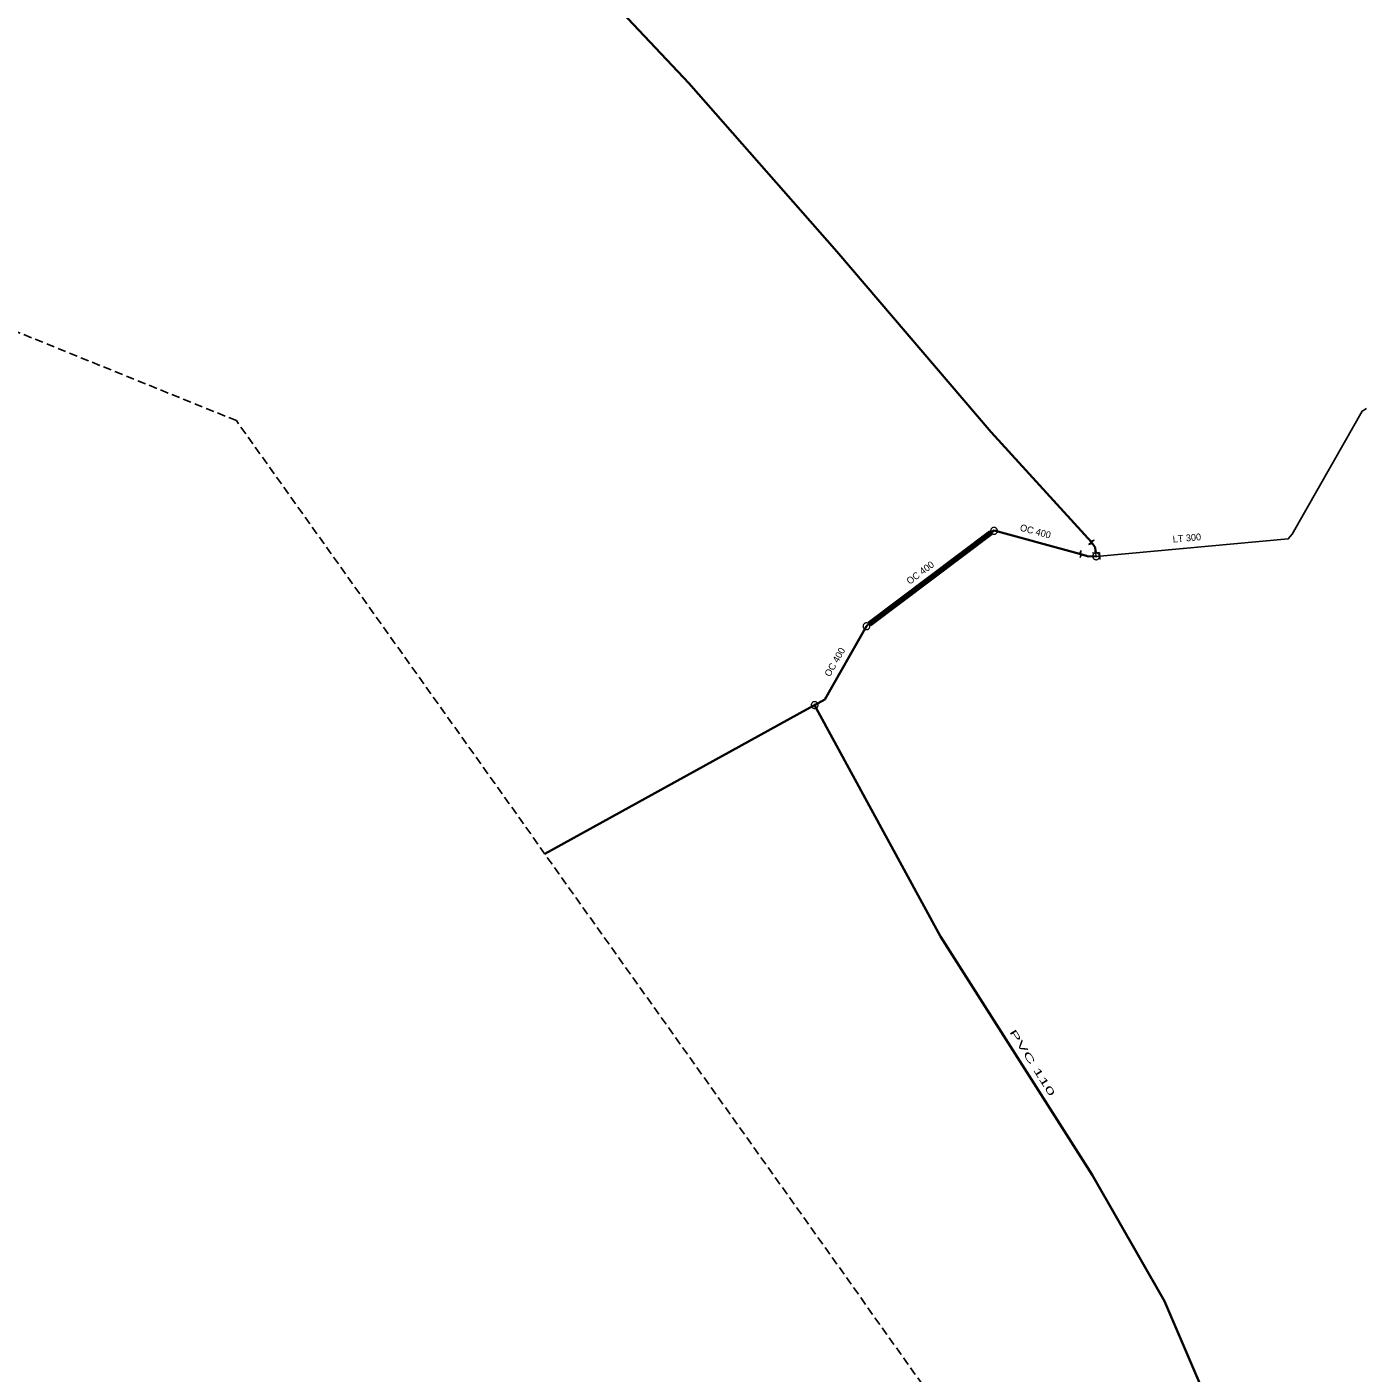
# Model space of a CAD drawing. Extents: x -724334 to -723692, y -972150 to -970648.
# Drawn here: x -724012.8 to -723816.8, y -971399.3 to -971202 of the extents above; entities that cross this region are included whole.
import ezdxf

# ---------------------------------------------------------------- set-up
doc = ezdxf.new("R2010")
doc.units = 0
doc.header["$LTSCALE"] = 0.4
doc.linetypes.add('MEDIUM_DASHED', pattern=[4.5, 3, -1.5])
for name, color, linetype, lineweight in [('1', 7, 'Continuous', 25), ('14', 7, 'Continuous', 25), ('17', 7, 'Continuous', 35), ('23', 7, 'Continuous', 13), ('3', 7, 'Continuous', 106), ('34', 7, 'Continuous', 13), ('47', 7, 'Continuous', 13)]:
    doc.layers.add(name, color=color, linetype=linetype, lineweight=lineweight)

msp = doc.modelspace()

# ---------------------------------------------------------------- linework, layer by layer
at = {"layer": '1', "linetype": 'MEDIUM_DASHED'}
msp.add_lwpolyline([(-723848.074, -970648.428), (-723714.095, -970720.999), (-724065.788, -971064.318), (-723792.249, -971201.088), (-723702.93, -971508.122), (-723691.766, -972150.101), (-723842.491, -972097.068), (-723864.821, -971424.385), (-723982.052, -971259.703), (-724333.745, -971117.352)], close=True, dxfattribs=at)
at = {"layer": '14', "lineweight": 13}
for q in [(-723856.14, -971279.03), (-723855.55, -971279.539)]:
    msp.add_line((-723856.079, -971279.579), q, dxfattribs=at)
at = {"layer": '17'}
for points in [[(-723856.75, -971277.52), (-723871.469, -971261.379), (-723894.09, -971234.91), (-723915.739, -971210.25), (-723934.449, -971190.379), (-723958.59, -971177.719), (-723983.8, -971165.17), (-724007.629, -971153.55), (-724038.03, -971139.35), (-724069.469, -971127.41), (-724098.62, -971120.079), (-724100.07, -971119.51), (-724120.89, -971115.66), (-724149.294, -971109.225), (-724187.32, -971097.32), (-724220.714, -971087.254)], [(-723889.699, -971289.809), (-723889.26, -971289.449), (-723871.489, -971276.09), (-723871.01, -971275.82)], [(-723871.01, -971275.82), (-723858.829, -971279.129), (-723858.359, -971279.26)], [(-723856.14, -971279.03), (-723856.17, -971278.77), (-723856.23, -971278.289), (-723856.75, -971277.52)], [(-723858.359, -971279.26), (-723857.5, -971279.51), (-723857.25, -971279.629), (-723856.079, -971279.579)], [(-723897.32, -971301.379), (-723895.809, -971300.579), (-723889.699, -971289.809)], [(-723936.882, -971323.157), (-723898.52, -971302.02), (-723897.32, -971301.379)], [(-723897.32, -971301.379), (-723897.12, -971301.809), (-723878.899, -971335.289), (-723856.64, -971370.239), (-723846.059, -971388.75), (-723832.309, -971420.76), (-723822.829, -971446.28), (-723817.91, -971463.35), (-723817.129, -971471.1), (-723816.85, -971479.71), (-723817.559, -971487.479)]]:
    msp.add_lwpolyline(points, dxfattribs=at)
at = {"layer": '17', "lineweight": 25}
msp.add_lwpolyline([(-723855.55, -971279.539), (-723827.91, -971277.02), (-723827.35, -971276.35), (-723819.71, -971262.93), (-723817.079, -971258.3), (-723816.43, -971257.91)], dxfattribs=at)
at = {"layer": '23'}
for points in [[(-723870.533, -971275.837), (-723870.536, -971275.784), (-723870.545, -971275.732), (-723870.56, -971275.683), (-723870.579, -971275.634), (-723870.603, -971275.588), (-723870.633, -971275.544), (-723870.666, -971275.504), (-723870.703, -971275.468), (-723870.744, -971275.435), (-723870.788, -971275.407), (-723870.835, -971275.383), (-723870.885, -971275.365), (-723870.935, -971275.352), (-723870.986, -971275.345), (-723871.038, -971275.342), (-723871.092, -971275.346), (-723871.142, -971275.354), (-723871.194, -971275.369), (-723871.241, -971275.387), (-723871.288, -971275.411), (-723871.332, -971275.442), (-723871.372, -971275.475), (-723871.409, -971275.513), (-723871.442, -971275.553), (-723871.469, -971275.597), (-723871.492, -971275.645), (-723871.51, -971275.693), (-723871.523, -971275.744), (-723871.53, -971275.796), (-723871.533, -971275.848), (-723871.53, -971275.9), (-723871.521, -971275.952), (-723871.507, -971276.003), (-723871.488, -971276.051), (-723871.463, -971276.096), (-723871.434, -971276.14), (-723871.401, -971276.181), (-723871.363, -971276.218), (-723871.322, -971276.25)], [(-723871.194, -971275.369), (-723871.241, -971275.387), (-723871.288, -971275.411), (-723871.332, -971275.442), (-723871.372, -971275.475), (-723871.409, -971275.513), (-723871.442, -971275.553), (-723871.469, -971275.597), (-723871.492, -971275.645), (-723871.51, -971275.693), (-723871.523, -971275.744), (-723871.53, -971275.796), (-723871.533, -971275.848), (-723871.53, -971275.9), (-723871.521, -971275.952), (-723871.507, -971276.003), (-723871.488, -971276.051), (-723871.463, -971276.096), (-723871.434, -971276.14), (-723871.401, -971276.181), (-723871.363, -971276.218), (-723871.322, -971276.25), (-723871.279, -971276.278), (-723871.231, -971276.301), (-723871.183, -971276.32), (-723871.131, -971276.332), (-723871.08, -971276.339), (-723871.028, -971276.342), (-723870.976, -971276.338), (-723870.924, -971276.33), (-723870.873, -971276.316), (-723870.825, -971276.296), (-723870.778, -971276.272), (-723870.735, -971276.244), (-723870.695, -971276.209), (-723870.658, -971276.173), (-723870.626, -971276.132), (-723870.597, -971276.087), (-723870.574, -971276.04), (-723870.556, -971275.991)], [(-723871.322, -971276.25), (-723871.279, -971276.278), (-723871.231, -971276.301), (-723871.183, -971276.32), (-723871.131, -971276.332), (-723871.08, -971276.339), (-723871.028, -971276.342), (-723870.976, -971276.338), (-723870.924, -971276.33), (-723870.873, -971276.316), (-723870.825, -971276.296), (-723870.778, -971276.272), (-723870.735, -971276.244), (-723870.695, -971276.209), (-723870.658, -971276.173), (-723870.626, -971276.132), (-723870.597, -971276.087), (-723870.574, -971276.04), (-723870.556, -971275.991), (-723870.544, -971275.94), (-723870.536, -971275.889), (-723870.533, -971275.837), (-723870.536, -971275.784), (-723870.545, -971275.732), (-723870.56, -971275.683), (-723870.579, -971275.634), (-723870.603, -971275.588), (-723870.633, -971275.544), (-723870.666, -971275.504), (-723870.703, -971275.468), (-723870.744, -971275.435), (-723870.788, -971275.407), (-723870.835, -971275.383), (-723870.885, -971275.365), (-723870.935, -971275.352), (-723870.986, -971275.345), (-723871.038, -971275.342), (-723871.092, -971275.346), (-723871.142, -971275.354), (-723871.194, -971275.369)], [(-723870.556, -971275.991), (-723870.544, -971275.94), (-723870.536, -971275.889), (-723870.533, -971275.837)], [(-723889.223, -971289.827), (-723889.225, -971289.774), (-723889.235, -971289.722), (-723889.25, -971289.673), (-723889.269, -971289.624), (-723889.293, -971289.578), (-723889.323, -971289.534), (-723889.355, -971289.494), (-723889.392, -971289.458), (-723889.434, -971289.425), (-723889.478, -971289.397), (-723889.524, -971289.373), (-723889.575, -971289.355), (-723889.625, -971289.342), (-723889.676, -971289.335), (-723889.728, -971289.332), (-723889.782, -971289.336), (-723889.831, -971289.344), (-723889.884, -971289.359), (-723889.931, -971289.377), (-723889.978, -971289.401), (-723890.022, -971289.432), (-723890.061, -971289.465), (-723890.098, -971289.503), (-723890.132, -971289.543), (-723890.159, -971289.587), (-723890.181, -971289.635), (-723890.2, -971289.683), (-723890.213, -971289.734), (-723890.22, -971289.786), (-723890.223, -971289.838), (-723890.22, -971289.89), (-723890.211, -971289.942), (-723890.196, -971289.993), (-723890.178, -971290.041), (-723890.152, -971290.086), (-723890.124, -971290.13), (-723890.09, -971290.171), (-723890.053, -971290.208), (-723890.012, -971290.24)], [(-723889.884, -971289.359), (-723889.931, -971289.377), (-723889.978, -971289.401), (-723890.022, -971289.432), (-723890.061, -971289.465), (-723890.098, -971289.503), (-723890.132, -971289.543), (-723890.159, -971289.587), (-723890.181, -971289.635), (-723890.2, -971289.683), (-723890.213, -971289.734), (-723890.22, -971289.786), (-723890.223, -971289.838), (-723890.22, -971289.89), (-723890.211, -971289.942), (-723890.196, -971289.993), (-723890.178, -971290.041), (-723890.152, -971290.086), (-723890.124, -971290.13), (-723890.09, -971290.171), (-723890.053, -971290.208), (-723890.012, -971290.24), (-723889.968, -971290.268), (-723889.921, -971290.291), (-723889.872, -971290.31), (-723889.821, -971290.322), (-723889.769, -971290.329), (-723889.718, -971290.332), (-723889.666, -971290.328), (-723889.614, -971290.32), (-723889.563, -971290.306), (-723889.514, -971290.286), (-723889.468, -971290.262), (-723889.424, -971290.234), (-723889.385, -971290.199), (-723889.348, -971290.163), (-723889.316, -971290.122), (-723889.287, -971290.077), (-723889.264, -971290.03), (-723889.245, -971289.981)], [(-723890.012, -971290.24), (-723889.968, -971290.268), (-723889.921, -971290.291), (-723889.872, -971290.31), (-723889.821, -971290.322), (-723889.769, -971290.329), (-723889.718, -971290.332), (-723889.666, -971290.328), (-723889.614, -971290.32), (-723889.563, -971290.306), (-723889.514, -971290.286), (-723889.468, -971290.262), (-723889.424, -971290.234), (-723889.385, -971290.199), (-723889.348, -971290.163), (-723889.316, -971290.122), (-723889.287, -971290.077), (-723889.264, -971290.03), (-723889.245, -971289.981), (-723889.233, -971289.93), (-723889.225, -971289.879), (-723889.223, -971289.827), (-723889.225, -971289.774), (-723889.235, -971289.722), (-723889.25, -971289.673), (-723889.269, -971289.624), (-723889.293, -971289.578), (-723889.323, -971289.534), (-723889.355, -971289.494), (-723889.392, -971289.458), (-723889.434, -971289.425), (-723889.478, -971289.397), (-723889.524, -971289.373), (-723889.575, -971289.355), (-723889.625, -971289.342), (-723889.676, -971289.335), (-723889.728, -971289.332), (-723889.782, -971289.336), (-723889.831, -971289.344), (-723889.884, -971289.359)], [(-723889.245, -971289.981), (-723889.233, -971289.93), (-723889.225, -971289.879), (-723889.223, -971289.827)]]:
    msp.add_lwpolyline(points, dxfattribs=at)
at = {"layer": '3'}
msp.add_line((-723889.26, -971289.45), (-723871.49, -971276.09), dxfattribs=at)
at = {"layer": '3', "lineweight": 100}
msp.add_line((-723889.26, -971289.45), (-723871.49, -971276.09), dxfattribs=at)
at = {"layer": '34'}
for p, q in [((-723856.636, -971279.084), (-723855.642, -971278.976)), ((-723855.588, -971279.04), (-723855.512, -971280.037))]:
    msp.add_line(p, q, dxfattribs=at)
at = {"layer": '47'}
for p, q in [((-723856.351, -971277.202), (-723856.842, -971277.341)), ((-723858.32, -971278.751), (-723858.552, -971279.206))]:
    msp.add_line(p, q, dxfattribs=at)
for points in [[(-723856.351, -971277.202), (-723857.148, -971277.837), (-723856.657, -971277.698)], [(-723858.32, -971278.751), (-723858.397, -971279.768), (-723858.165, -971279.313)]]:
    msp.add_lwpolyline(points, dxfattribs=at)
for points in [[(-723855.579, -971279.557), (-723855.584, -971279.505), (-723855.594, -971279.454), (-723855.611, -971279.404), (-723855.631, -971279.356), (-723855.657, -971279.31), (-723855.687, -971279.268), (-723855.722, -971279.229), (-723855.761, -971279.194), (-723855.802, -971279.162), (-723855.847, -971279.135), (-723855.895, -971279.113), (-723855.945, -971279.097), (-723855.995, -971279.086), (-723856.048, -971279.08), (-723856.1, -971279.079), (-723856.152, -971279.084), (-723856.203, -971279.094), (-723856.254, -971279.111), (-723856.301, -971279.131), (-723856.347, -971279.157), (-723856.389, -971279.187), (-723856.429, -971279.222), (-723856.464, -971279.261), (-723856.496, -971279.302), (-723856.522, -971279.347), (-723856.544, -971279.395), (-723856.561, -971279.445), (-723856.571, -971279.495), (-723856.577, -971279.548), (-723856.578, -971279.6), (-723856.573, -971279.652), (-723856.563, -971279.703), (-723856.547, -971279.754), (-723856.526, -971279.801), (-723856.5, -971279.847), (-723856.471, -971279.89), (-723856.436, -971279.929), (-723856.397, -971279.964), (-723856.355, -971279.996), (-723856.31, -971280.022), (-723856.262, -971280.044), (-723856.213, -971280.061), (-723856.162, -971280.071), (-723856.109, -971280.077), (-723856.057, -971280.078), (-723856.005, -971280.073), (-723855.954, -971280.063), (-723855.904, -971280.047), (-723855.856, -971280.026), (-723855.81, -971280), (-723855.767, -971279.971), (-723855.729, -971279.936), (-723855.694, -971279.897), (-723855.662, -971279.855), (-723855.635, -971279.81), (-723855.613, -971279.762), (-723855.597, -971279.713), (-723855.586, -971279.662), (-723855.58, -971279.609)], [(-723855.997, -971279.575), (-723855.997, -971279.566), (-723855.999, -971279.558), (-723856.002, -971279.55), (-723856.005, -971279.542), (-723856.009, -971279.535), (-723856.015, -971279.528), (-723856.02, -971279.521), (-723856.026, -971279.515), (-723856.033, -971279.511), (-723856.041, -971279.506), (-723856.049, -971279.502), (-723856.057, -971279.5), (-723856.065, -971279.498), (-723856.073, -971279.496), (-723856.082, -971279.497), (-723856.091, -971279.497), (-723856.099, -971279.499), (-723856.107, -971279.502), (-723856.115, -971279.505), (-723856.122, -971279.509), (-723856.129, -971279.515), (-723856.136, -971279.52), (-723856.142, -971279.526), (-723856.147, -971279.533), (-723856.151, -971279.541), (-723856.155, -971279.549), (-723856.157, -971279.557), (-723856.159, -971279.565), (-723856.161, -971279.573), (-723856.16, -971279.582), (-723856.16, -971279.591), (-723856.158, -971279.599), (-723856.155, -971279.607), (-723856.152, -971279.615), (-723856.148, -971279.622), (-723856.143, -971279.629), (-723856.137, -971279.636), (-723856.131, -971279.642), (-723856.124, -971279.647), (-723856.116, -971279.651), (-723856.108, -971279.655), (-723856.1, -971279.657), (-723856.092, -971279.659), (-723856.084, -971279.661), (-723856.075, -971279.66), (-723856.066, -971279.66), (-723856.058, -971279.658), (-723856.05, -971279.655), (-723856.042, -971279.652), (-723856.035, -971279.648), (-723856.028, -971279.643), (-723856.021, -971279.637), (-723856.015, -971279.631), (-723856.011, -971279.624), (-723856.006, -971279.616), (-723856.002, -971279.608), (-723856, -971279.6), (-723855.998, -971279.592), (-723855.996, -971279.584)], [(-723896.82, -971301.38), (-723896.823, -971301.328), (-723896.831, -971301.276), (-723896.845, -971301.226), (-723896.862, -971301.177), (-723896.887, -971301.13), (-723896.916, -971301.086), (-723896.948, -971301.046), (-723896.985, -971301.009), (-723897.026, -971300.976), (-723897.07, -971300.947), (-723897.117, -971300.923), (-723897.166, -971300.905), (-723897.215, -971300.891), (-723897.267, -971300.883), (-723897.32, -971300.88), (-723897.372, -971300.883), (-723897.424, -971300.891), (-723897.475, -971300.905), (-723897.522, -971300.923), (-723897.57, -971300.947), (-723897.614, -971300.976), (-723897.654, -971301.009), (-723897.691, -971301.046), (-723897.725, -971301.086), (-723897.752, -971301.13), (-723897.777, -971301.177), (-723897.796, -971301.226), (-723897.808, -971301.276), (-723897.816, -971301.328), (-723897.82, -971301.38), (-723897.816, -971301.432), (-723897.808, -971301.484), (-723897.796, -971301.535), (-723897.777, -971301.583), (-723897.752, -971301.63), (-723897.725, -971301.674), (-723897.691, -971301.715), (-723897.654, -971301.752), (-723897.614, -971301.785), (-723897.57, -971301.813), (-723897.522, -971301.837), (-723897.475, -971301.856), (-723897.424, -971301.869), (-723897.372, -971301.877), (-723897.32, -971301.88), (-723897.267, -971301.877), (-723897.215, -971301.869), (-723897.166, -971301.856), (-723897.117, -971301.837), (-723897.07, -971301.813), (-723897.026, -971301.785), (-723896.985, -971301.752), (-723896.948, -971301.715), (-723896.916, -971301.674), (-723896.887, -971301.63), (-723896.862, -971301.583), (-723896.845, -971301.535), (-723896.831, -971301.484), (-723896.823, -971301.432)], [(-723897.237, -971301.38), (-723897.237, -971301.371), (-723897.24, -971301.363), (-723897.242, -971301.355), (-723897.245, -971301.347), (-723897.249, -971301.339), (-723897.254, -971301.332), (-723897.259, -971301.325), (-723897.264, -971301.319), (-723897.272, -971301.314), (-723897.279, -971301.309), (-723897.286, -971301.305), (-723897.294, -971301.302), (-723897.303, -971301.3), (-723897.311, -971301.298), (-723897.32, -971301.298), (-723897.328, -971301.298), (-723897.337, -971301.3), (-723897.345, -971301.302), (-723897.353, -971301.305), (-723897.36, -971301.309), (-723897.367, -971301.314), (-723897.375, -971301.319), (-723897.38, -971301.325), (-723897.387, -971301.332), (-723897.391, -971301.339), (-723897.394, -971301.347), (-723897.397, -971301.355), (-723897.399, -971301.363), (-723897.402, -971301.371), (-723897.402, -971301.38), (-723897.402, -971301.389), (-723897.399, -971301.397), (-723897.397, -971301.405), (-723897.394, -971301.413), (-723897.391, -971301.421), (-723897.387, -971301.428), (-723897.38, -971301.435), (-723897.375, -971301.441), (-723897.367, -971301.447), (-723897.36, -971301.451), (-723897.353, -971301.455), (-723897.345, -971301.458), (-723897.337, -971301.46), (-723897.328, -971301.462), (-723897.32, -971301.462), (-723897.311, -971301.462), (-723897.303, -971301.46), (-723897.294, -971301.458), (-723897.286, -971301.455), (-723897.279, -971301.451), (-723897.272, -971301.447), (-723897.264, -971301.441), (-723897.259, -971301.435), (-723897.254, -971301.428), (-723897.249, -971301.421), (-723897.245, -971301.413), (-723897.242, -971301.405), (-723897.24, -971301.397), (-723897.237, -971301.389)]]:
    msp.add_lwpolyline(points, close=True, dxfattribs=at)

# ---------------------------------------------------------------- texts
at = {"layer": '1'}
for s, rotation, p in [('OC 400', 345, (-723867.32, -971275.799)), ('LT 300', 5, (-723844.806, -971277.57)), ('OC 400', 37, (-723883.389, -971283.766)), ('OC 400', 60, (-723895.091, -971297.318))]:
    msp.add_text(s, height=1, rotation=rotation, dxfattribs=at).set_placement(p)
at = {"layer": '1', "width": 2.1}
msp.add_text('PVC 110 ', height=1, rotation=302, dxfattribs=at).set_placement((-723868.818, -971349.283))

doc.saveas('drawing.dxf')
